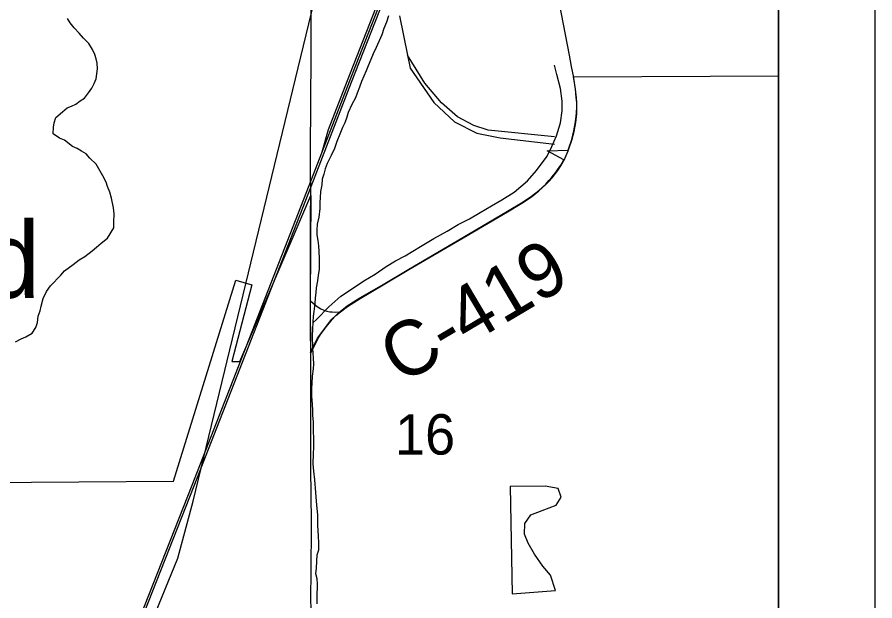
# Model space of a CAD drawing. Extents: x 0 to 34, y 0 to 22.
# Drawn here: x 8.111 to 9, y 18.515 to 19.12 of the extents above; entities that cross this region are included whole.
import ezdxf

# ---------------------------------------------------------------- set-up
doc = ezdxf.new("R2010")
doc.units = 0
for name, color, linetype in [('GM_X_County_Road', 7, 'Continuous'), ('GM_X_County_Road_Text', 7, 'Continuous'), ('GM_X_Minor_Lake', 7, 'Continuous'), ('GM_X_Minor_River', 7, 'Continuous'), ('GM_X_Rail_Line', 7, 'Continuous'), ('GM_X_Section_Text', 7, 'Continuous'), ('GM_X_State_Route', 7, 'Continuous'), ('GM_X_Township_Road', 7, 'Continuous'), ('GM_X_Unincorporated', 7, 'Continuous'), ('GM_X_Unincorporated_Text', 7, 'Continuous'), ('SH_Data', 7, 'Continuous')]:
    doc.layers.add(name, color=color, linetype=linetype)

msp = doc.modelspace()

# ---------------------------------------------------------------- linework, layer by layer
at = {"layer": 'GM_X_County_Road'}
for points in [[(8.68796, 19.05659), (8.68781, 19.05754), (8.68565, 19.06883), (8.68344, 19.08039), (8.66662, 19.16837)], [(8.415, 18.96559), (8.415, 18.97174), (8.41504, 18.99361), (8.41544, 19.01858), (8.41529, 19.03083), (8.41586, 19.0808), (8.41563, 19.10269), (8.41574, 19.12455), (8.4158, 19.13975), (8.41585, 19.15044)], [(8.68216, 18.98149), (8.68296, 18.98356), (8.68602, 18.99244), (8.68829, 19.00152), (8.69007, 19.01079), (8.69106, 19.01986), (8.69126, 19.02658), (8.69116, 19.03101), (8.69077, 19.03624), (8.68978, 19.04522), (8.68796, 19.05659)], [(8.67742, 18.97075), (8.67788, 18.97155), (8.68216, 18.98149)], [(8.41542, 18.93455), (8.41531, 18.93982), (8.41508, 18.95857), (8.415, 18.96559)], [(8.44601, 18.81443), (8.45338, 18.82003), (8.46638, 18.82833), (8.49044, 18.84239), (8.51707, 18.85821), (8.57312, 18.89113), (8.61931, 18.91815), (8.63391, 18.92703), (8.64427, 18.93384), (8.65177, 18.93975), (8.65908, 18.94636), (8.66228, 18.94991), (8.66549, 18.95346), (8.66894, 18.95781), (8.67131, 18.96106), (8.67464, 18.966), (8.67742, 18.97075)], [(8.4149, 18.82577), (8.41501, 18.88055), (8.41499, 18.91482), (8.41542, 18.93455)], [(8.41531, 18.77163), (8.41485, 18.79646), (8.4149, 18.82577)], [(8.4149, 18.82577), (8.42021, 18.8215), (8.42286, 18.81937), (8.42571, 18.8177), (8.42874, 18.81634), (8.43188, 18.81529), (8.43511, 18.81458), (8.43741, 18.81436), (8.44138, 18.81419), (8.44601, 18.81443)], [(8.41531, 18.77163), (8.42261, 18.78661), (8.42608, 18.7919), (8.43151, 18.7993), (8.43743, 18.8064), (8.44138, 18.81064), (8.44601, 18.81443)], [(8.41698, 18.23261), (8.41652, 18.29303), (8.41637, 18.32712), (8.41584, 18.39526), (8.41563, 18.42936), (8.41579, 18.47273), (8.41565, 18.5006), (8.41553, 18.5223), (8.41588, 18.54089), (8.41602, 18.59664), (8.41538, 18.6524), (8.4155, 18.70197), (8.41544, 18.73914), (8.41531, 18.77163)]]:
    msp.add_lwpolyline(points, dxfattribs=at)
at = {"layer": 'GM_X_Minor_Lake'}
for points in [[(8.62403, 18.52227), (8.66907, 18.52564), (8.66366, 18.54153), (8.65602, 18.55095), (8.64723, 18.5634), (8.64071, 18.57473), (8.63686, 18.58418), (8.63716, 18.59518), (8.64354, 18.60395), (8.65525, 18.60859), (8.6696, 18.61401), (8.67485, 18.62239), (8.67175, 18.63147), (8.6581, 18.63364), (8.62212, 18.63337)], [(8.62212, 18.63337), (8.62403, 18.52227)]]:
    msp.add_lwpolyline(points, dxfattribs=at)
at = {"layer": 'GM_X_Minor_River'}
for points in [[(8.10923, 18.78344), (8.11527, 18.78655), (8.11981, 18.78851), (8.12661, 18.7924), (8.13034, 18.79815), (8.13217, 18.80349), (8.13285, 18.80996), (8.13467, 18.81568), (8.13575, 18.82025), (8.13793, 18.82826), (8.14126, 18.83552), (8.14537, 18.84128), (8.15625, 18.85244), (8.16, 18.85704), (8.16904, 18.86362), (8.17507, 18.86826), (8.1811, 18.87176), (8.18864, 18.87756), (8.19315, 18.88142), (8.19804, 18.88566), (8.20444, 18.89068), (8.21115, 18.90141), (8.21107, 18.90711), (8.21134, 18.91623), (8.21088, 18.9223), (8.20885, 18.93215), (8.20686, 18.93858), (8.20451, 18.94424), (8.20331, 18.94879), (8.19979, 18.95558), (8.19552, 18.96274), (8.19279, 18.96764), (8.18625, 18.97363), (8.18239, 18.97814), (8.17778, 18.98112), (8.17319, 18.98371), (8.16821, 18.98593), (8.16014, 18.99228), (8.15479, 18.99448), (8.14827, 18.99896), (8.14856, 19.0058), (8.14926, 19.01037), (8.15109, 19.01609), (8.15786, 19.02187), (8.16275, 19.02612), (8.16729, 19.0277), (8.17183, 19.02966), (8.17635, 19.03314), (8.18088, 19.03586), (8.18499, 19.04161), (8.18835, 19.04621), (8.19095, 19.05118), (8.19278, 19.05615), (8.19348, 19.06109), (8.19417, 19.06642), (8.19372, 19.07211), (8.1929, 19.07666), (8.19132, 19.0812), (8.18897, 19.08649), (8.18509, 19.09251), (8.17969, 19.09814), (8.17506, 19.10339), (8.17004, 19.10903), (8.16579, 19.11391), (8.16307, 19.11843)], [(8.49583, 19.12134), (8.49363, 19.11485), (8.49105, 19.10836), (8.48886, 19.10149), (8.48294, 19.0885), (8.47998, 19.082), (8.4774, 19.07589), (8.47482, 19.0694), (8.4726, 19.06443), (8.4704, 19.0587), (8.46781, 19.05335), (8.46598, 19.04725), (8.4634, 19.04114), (8.46156, 19.03617), (8.45785, 19.02929), (8.45415, 19.02126), (8.45269, 19.0163), (8.45049, 19.01057), (8.44827, 19.00561), (8.44531, 18.99873), (8.44237, 18.99109), (8.4398, 18.98384), (8.43647, 18.97658), (8.4324, 18.96817), (8.43018, 18.96282), (8.42874, 18.95711), (8.42728, 18.95215), (8.4266, 18.94606), (8.42555, 18.93921), (8.42487, 18.93312), (8.42456, 18.9278), (8.42463, 18.92172), (8.42361, 18.91259), (8.4218, 18.90535), (8.4215, 18.89927), (8.42157, 18.89433), (8.42278, 18.88827), (8.42324, 18.88296), (8.42369, 18.87689), (8.42417, 18.86968), (8.42385, 18.86473), (8.42394, 18.85828), (8.42287, 18.85257), (8.42219, 18.84648), (8.42076, 18.83924), (8.42044, 18.8343), (8.41975, 18.82897), (8.41945, 18.82327), (8.41841, 18.8149), (8.41772, 18.80957), (8.41741, 18.80425), (8.41713, 18.79665)], [(8.41737, 18.80323), (8.42133, 18.8067), (8.43412, 18.81969), (8.44654, 18.83078), (8.45748, 18.83807), (8.47029, 18.84651), (8.48199, 18.85342), (8.49329, 18.86147), (8.5031, 18.86723), (8.51329, 18.87262), (8.52913, 18.88222), (8.54271, 18.89066), (8.55667, 18.89797), (8.56799, 18.90489), (8.57968, 18.91104), (8.591, 18.91757), (8.60269, 18.92449), (8.61326, 18.93064), (8.62608, 18.93869), (8.64001, 18.95018), (8.64941, 18.96087), (8.66029, 18.97574), (8.66514, 18.98601), (8.66999, 18.99705), (8.67407, 19.01035), (8.67587, 19.02288), (8.67581, 19.03274), (8.6742, 19.046), (8.67031, 19.06039), (8.66797, 19.07023)], [(8.41713, 18.79665), (8.41684, 18.78981), (8.417, 18.77689), (8.41745, 18.77158), (8.4179, 18.76665), (8.41798, 18.7602), (8.41767, 18.75525), (8.41663, 18.74764), (8.41634, 18.74042), (8.41603, 18.7351), (8.41614, 18.72674), (8.41662, 18.71877), (8.41708, 18.71232), (8.41715, 18.70738), (8.41762, 18.70017), (8.41796, 18.67397), (8.41767, 18.6675), (8.41742, 18.65686), (8.41828, 18.64928), (8.41916, 18.64018), (8.42009, 18.62727), (8.42097, 18.61817), (8.42145, 18.61057), (8.42229, 18.60413), (8.42235, 18.59919), (8.42243, 18.5935), (8.42296, 18.58211), (8.42343, 18.57489), (8.42315, 18.56729), (8.42169, 18.56234), (8.42139, 18.55626), (8.42073, 18.54827), (8.42004, 18.54332), (8.42163, 18.53803), (8.42209, 18.53195), (8.42149, 18.51903), (8.42159, 18.51182)]]:
    msp.add_lwpolyline(points, dxfattribs=at)
at = {"layer": 'GM_X_Rail_Line'}
msp.add_line((8.50742, 19.12147), (8.51562, 19.08044), dxfattribs=at)
for points in [[(8.42712, 18.98036), (8.43359, 19.00347), (8.4533, 19.05412), (8.53216, 19.25558), (8.58729, 19.39608), (8.61213, 19.46075), (8.63198, 19.51134), (8.64379, 19.53981), (8.65647, 19.56535), (8.67101, 19.59304), (8.68569, 19.61947), (8.69776, 19.64136), (8.73605, 19.7107), (8.78054, 19.79055), (8.82175, 19.86452), (8.84841, 19.91337), (8.8647, 19.94732), (8.8788, 19.98015), (8.9, 20.03044)], [(7.88643, 17.59932), (7.90898, 17.6604), (8.00201, 17.89866), (8.29237, 18.63494), (8.4135, 18.9454), (8.4555, 19.05327), (8.53436, 19.25473), (8.58949, 19.39524), (8.61432, 19.45991), (8.63417, 19.51046), (8.64593, 19.53884), (8.65857, 19.56429), (8.67308, 19.59193), (8.68775, 19.61833), (8.69982, 19.64023), (8.73811, 19.70956), (8.7826, 19.78941), (8.82382, 19.86339), (8.85051, 19.9123), (8.86685, 19.94635), (8.88097, 19.97923), (8.9, 20.02438)], [(7.75733, 17.27239), (7.85176, 17.51498), (7.91117, 17.65953), (8.0042, 17.8978), (8.29457, 18.63409), (8.4157, 18.94455), (8.45769, 19.05242), (8.53655, 19.25388), (8.59169, 19.39439), (8.61652, 19.45906), (8.63635, 19.50959), (8.64808, 19.53787), (8.66067, 19.56322), (8.67516, 19.59082), (8.68982, 19.6172), (8.70189, 19.6391), (8.74017, 19.70843), (8.78466, 19.78827), (8.82588, 19.86226), (8.85261, 19.91123), (8.86899, 19.94538), (8.88314, 19.97832), (8.9, 20.01832)], [(6.46064, 14.09996), (6.45713, 14.19536), (6.44773, 14.44053), (6.45238, 14.50813), (6.46367, 14.55678), (6.48566, 14.6083), (6.54727, 14.69788), (6.88614, 15.13086), (7.24057, 15.57245), (7.33381, 15.68245), (7.38513, 15.75625), (7.42249, 15.82237), (7.44954, 15.91319), (7.4686, 16.00837), (7.58162, 16.56482), (7.64362, 16.88689), (7.66845, 17.00953), (7.69755, 17.09135), (7.75798, 17.24541), (8.00835, 17.8807), (8.14941, 18.24545), (8.27735, 18.55925), (8.29339, 18.61839), (8.45401, 19.28155)], [(8.66805, 18.99599), (8.59911, 19.0027), (8.58443, 19.00758), (8.56753, 19.01679), (8.55092, 19.03098), (8.53365, 19.05168), (8.51562, 19.08044)], [(8.51562, 19.08044), (8.51828, 19.06711), (8.54281, 19.03155), (8.56445, 19.0115), (8.58759, 18.99984), (8.61163, 18.99471), (8.66809, 18.98823)]]:
    msp.add_lwpolyline(points, dxfattribs=at)
at = {"layer": 'GM_X_State_Route'}
msp.add_lwpolyline([(7.97843, 18.63678), (8.27306, 18.63894), (8.33759, 18.84729), (8.35438, 18.84256), (8.33358, 18.76299), (8.34176, 18.76303), (8.41521, 18.9351), (8.41469, 18.82632), (8.4151, 18.77217), (8.4224, 18.78716), (8.43722, 18.80695), (8.4458, 18.81498), (8.4461, 18.81524), (8.45317, 18.82057), (8.46617, 18.82887), (8.49023, 18.84294), (8.51686, 18.85876), (8.57291, 18.89168), (8.6191, 18.9187), (8.6337, 18.92758), (8.64406, 18.93438), (8.65156, 18.9403), (8.65887, 18.94691), (8.66207, 18.95046), (8.66528, 18.95401), (8.66873, 18.95836), (8.6711, 18.96161), (8.67443, 18.96655), (8.67767, 18.97209), (8.66033, 18.98138), (8.68195, 18.98204), (8.68275, 18.9841), (8.68581, 18.99298), (8.68808, 19.00206), (8.68986, 19.01133), (8.69085, 19.02041), (8.69105, 19.02712), (8.69095, 19.03156), (8.69056, 19.03679), (8.68957, 19.04577), (8.6876, 19.05809), (8.9, 19.05919), (8.9, 20.89996)], dxfattribs=at)
at = {"layer": 'GM_X_Township_Road'}
msp.add_lwpolyline([(8.9, 17.26338), (8.9, 20.89996), (5.78179, 20.89996)], dxfattribs=at)
at = {"layer": 'GM_X_Unincorporated'}
msp.add_lwpolyline([(8.9, 18.27692), (8.9, 19.27567), (7.90787, 19.27209), (7.92171, 18.27008)], close=True, dxfattribs=at)
at = {"layer": 'SH_Data'}
for p, q in [((9, 20.99996), (9, 13.99996)), ((8.9, 20.89996), (8.9, 14.09996))]:
    msp.add_line(p, q, dxfattribs=at)

# ---------------------------------------------------------------- texts
at = {"layer": 'GM_X_County_Road_Text'}
msp.add_text('C-419', height=0.056818, rotation=30.69218, dxfattribs=at).set_placement((8.50921, 18.73843))
at = {"layer": 'GM_X_Section_Text'}
msp.add_text('16', height=0.041856, rotation=0.00001, dxfattribs=at).set_placement((8.50265, 18.66652))
at = {"layer": 'GM_X_Unincorporated_Text'}
msp.add_text('Westwood', height=0.078977, rotation=0.00001, dxfattribs=at).set_placement((7.64182, 18.82891))

doc.saveas('drawing.dxf')
